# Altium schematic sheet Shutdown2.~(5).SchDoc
size A4
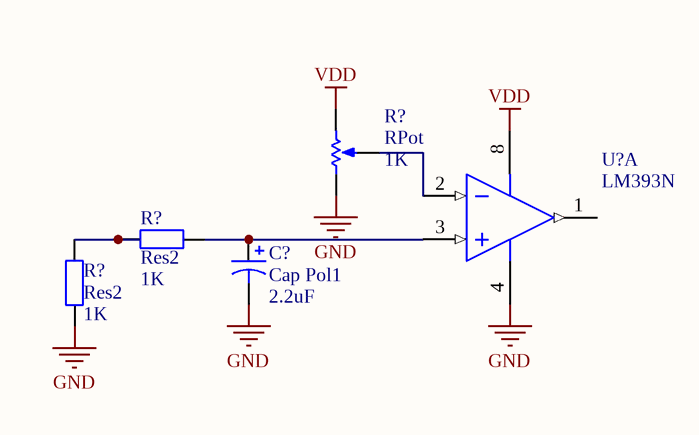
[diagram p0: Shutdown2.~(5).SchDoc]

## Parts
(Parts that share a designator on the sheet are numbered #1, #2 ... from top to bottom, then left to right.)
C?  Cap Pol1  value 2.2uF  [RB7.6-15]
R?#1  RPot  value 1K  [VR5]
R?#2  Res2  value 1K  [AXIAL-0.4]
R?#3  Res2  value 1K  [AXIAL-0.4]
U?  LM393N  [626-05]  (part A of 2)

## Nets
GND: C?.2 R?#1.1(TOP) R?#3.1 U?.4(GND)
VDD: R?#1.2(BOT) U?.8(V+)
NetC?_1: C?.1 R?#2.2 U?.3(IN+)
NetR?#1_3: R?#1.3(TAP) U?.2(IN-)
NetR?#2_1: R?#2.1 R?#3.2

Not connected (* = marked no-connect by the designer): U? 1(OUT)

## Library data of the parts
C? = Cap Pol1: Polarized Capacitor (Radial)
R?#1 = RPot: Potentiometer; Sim Note: Enter the Resistance value and the set point into parameter fields.; Set Position: 0.5
R?#2 R?#3 = Res2: Resistor
U? = LM393N: Dual Comparator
